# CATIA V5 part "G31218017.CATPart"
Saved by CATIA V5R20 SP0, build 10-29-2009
Part number: G31218017
Revision: 6
Definition: design
Nomenclature: G31218017
Source: made
Description: NOT SPECIFIED
Bounding box of the stored display mesh (mm): x -8 to 17, y -15.5 to 15.5, z -15.5 to 15.5
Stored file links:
  C:\Users\Raffaele\Desktop\3D X SITO CF\BOLEX\23-BUSH REF 312\G31218017.CATPart

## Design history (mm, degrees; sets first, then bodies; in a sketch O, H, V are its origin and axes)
Body1 "MANIFOLD_SOLID_BREP #3823" (main body)
  Solid1: solid without history
Body2 "MANIFOLD_SOLID_BREP #3966"
  Solid2: solid without history
Body3 "MANIFOLD_SOLID_BREP #4109"
  Solid3: solid without history
Body4 "MANIFOLD_SOLID_BREP #4252"
  Solid4: solid without history
Body5 "MANIFOLD_SOLID_BREP #4395"
  Solid5: solid without history
Body6 "MANIFOLD_SOLID_BREP #4540"
  Solid6: solid without history
Body7 "MANIFOLD_SOLID_BREP #4685"
  Solid7: solid without history
Body8 "MANIFOLD_SOLID_BREP #4830"
  Solid8: solid without history
Body9 "MANIFOLD_SOLID_BREP #4975"
  Solid9: solid without history
Body10 "MANIFOLD_SOLID_BREP #5120"
  Solid10: solid without history
Body11 "MANIFOLD_SOLID_BREP #5265"
  Solid11: solid without history
Body12 "MANIFOLD_SOLID_BREP #5410"
  Solid12: solid without history
Body13 "MANIFOLD_SOLID_BREP #5555"
  Solid13: solid without history
Body14 "MANIFOLD_SOLID_BREP #5700"
  Solid14: solid without history
Body15 "MANIFOLD_SOLID_BREP #5845"
  Solid15: solid without history
Body16 "MANIFOLD_SOLID_BREP #5990"
  Solid16: solid without history
Body17 "MANIFOLD_SOLID_BREP #6135"
  Solid17: solid without history
Body18 "MANIFOLD_SOLID_BREP #6280"
  Solid18: solid without history
Body19 "MANIFOLD_SOLID_BREP #6425"
  Solid19: solid without history
Body20 "MANIFOLD_SOLID_BREP #6572"
  Solid20: solid without history
Body21 "MANIFOLD_SOLID_BREP #6719"
  Solid21: solid without history
Body22 "MANIFOLD_SOLID_BREP #6864"
  Solid22: solid without history
Body23 "MANIFOLD_SOLID_BREP #7011"
  Solid23: solid without history
Body24 "MANIFOLD_SOLID_BREP #7158"
  Solid24: solid without history
Body25 "MANIFOLD_SOLID_BREP #7303"
  Solid25: solid without history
